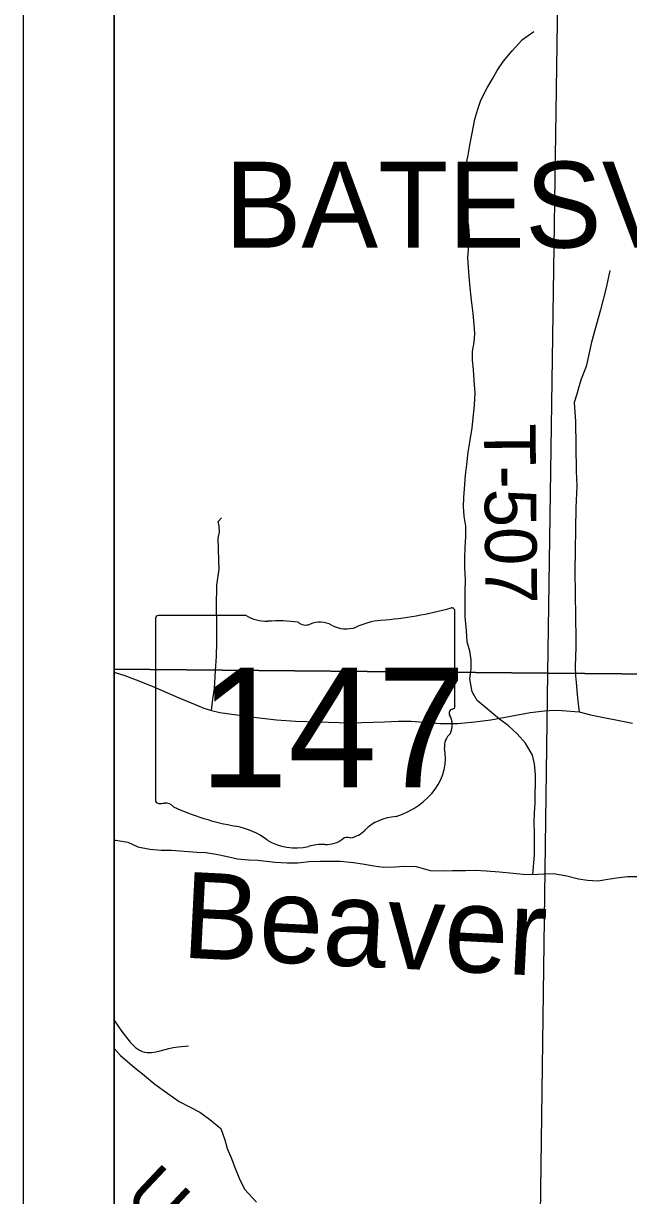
# Model space of a CAD drawing. Extents: x 0 to 34, y 0 to 22.
# Drawn here: x 23.417 to 24.083, y 17.051 to 18.342 of the extents above; entities that cross this region are included whole.
import ezdxf

# ---------------------------------------------------------------- set-up
doc = ezdxf.new("R2010")
doc.units = 0
for name, color, linetype in [('GM_X_Corporation', 7, 'Continuous'), ('GM_X_Corporation_Text', 7, 'Continuous'), ('GM_X_Minor_River', 7, 'Continuous'), ('GM_X_Minor_River_Text', 7, 'Continuous'), ('GM_X_State_Route', 7, 'Continuous'), ('GM_X_State_Shield', 7, 'Continuous'), ('GM_X_Township_Road', 7, 'Continuous'), ('GM_X_Township_Road_Text', 7, 'Continuous'), ('SH_Data', 7, 'Continuous')]:
    doc.layers.add(name, color=color, linetype=linetype)

msp = doc.modelspace()

# ---------------------------------------------------------------- linework, layer by layer
at = {"layer": 'GM_X_Corporation'}
msp.add_lwpolyline([(27.0234, 16.6611), (27.0349, 17.5522), (27.0419, 17.8236), (27.0487, 18.5805), (27.0719, 19.3912), (27.0733, 19.498), (27.0761, 19.6806), (27.0864, 20.0138), (27.0885, 20.1139), (27.0907, 20.123), (27.0873, 20.2665), (27.0031, 20.2673), (26.7822, 20.2704), (26.7196, 20.2707), (26.6351, 20.2734), (26.5702, 20.276), (26.2533, 20.2773), (25.4507, 20.2949), (24.5249, 20.3107), (24.0688, 20.3165), (24.0328, 20.3169), (23.5167, 20.3276), (23.5167, 14.5642)], dxfattribs=at)
msp.add_lwpolyline([(27.0234, 16.6611), (27.0349, 17.5522), (27.0419, 17.8236), (27.0487, 18.5805), (27.0719, 19.3912), (27.0733, 19.498), (27.0761, 19.6806), (27.0864, 20.0138), (27.0885, 20.1139), (27.0907, 20.123), (27.0873, 20.2665), (27.0031, 20.2673), (26.7822, 20.2704), (26.7196, 20.2707), (26.6351, 20.2734), (26.5702, 20.276), (26.2533, 20.2773), (25.4507, 20.2949), (24.5249, 20.3107), (24.0688, 20.3165), (24.0328, 20.3169), (23.5167, 20.3276), (23.5167, 14.5642)], dxfattribs=at)
for points in [[(23.5167, 18.6437), (23.5167, 17.6305), (23.994, 17.626), (24.0091, 18.6407)], [(24.0091, 18.6407), (25.0268, 18.6245), (25.0136, 17.617), (23.994, 17.626)], [(23.5167, 17.6305), (23.5167, 16.6012), (23.9803, 16.5962), (23.994, 17.626)], [(25.0136, 17.617), (24.9957, 16.5834), (23.9803, 16.5962), (23.994, 17.626)]]:
    msp.add_lwpolyline(points, close=True, dxfattribs=at)
at = {"layer": 'GM_X_Minor_River'}
for points in [[(23.9775, 17.4045), (23.9795, 17.4258), (23.9795, 17.4497), (23.9791, 17.4618), (23.9794, 17.4725), (23.9802, 17.4827), (23.9801, 17.4937), (23.9805, 17.5044), (23.9805, 17.5142), (23.9793, 17.5264), (23.9774, 17.5359), (23.9694, 17.5491), (23.9603, 17.5593), (23.9508, 17.568), (23.9409, 17.5756), (23.9165, 17.596), (23.9108, 17.6055), (23.9081, 17.6199), (23.9096, 17.6309), (23.9096, 17.6408), (23.9081, 17.6503), (23.9054, 17.6605), (23.9046, 17.6727), (23.903, 17.6886), (23.903, 17.716), (23.9033, 17.7289), (23.9029, 17.7421), (23.9029, 17.7535), (23.9032, 17.7646), (23.904, 17.7767), (23.9039, 17.7881), (23.902, 17.7991), (23.9012, 17.8097), (23.9016, 17.8196), (23.9023, 17.8291), (23.9034, 17.8443), (23.9049, 17.8561), (23.9064, 17.8697), (23.9083, 17.8808), (23.9109, 17.8963), (23.9124, 17.9108), (23.9135, 17.9214), (23.9142, 17.9351), (23.9131, 17.9487), (23.9123, 17.9605), (23.9111, 17.9711), (23.9111, 17.9806), (23.913, 17.9909), (23.9137, 18.0004), (23.9129, 18.0102), (23.9118, 18.0224), (23.9102, 18.0372), (23.9087, 18.0505), (23.9075, 18.063), (23.9067, 18.0729), (23.9059, 18.0839), (23.907, 18.0968), (23.9078, 18.1074), (23.907, 18.1181), (23.9058, 18.1276), (23.9046, 18.1397), (23.9031, 18.1526), (23.9019, 18.1636), (23.9023, 18.1743), (23.9038, 18.1845), (23.9064, 18.1967), (23.9083, 18.2077), (23.9109, 18.221), (23.9139, 18.2366), (23.9169, 18.2476), (23.9203, 18.2575), (23.9275, 18.2708), (23.9331, 18.2807), (23.9384, 18.2902), (23.9452, 18.3005), (23.9547, 18.3119), (23.9661, 18.3241), (23.9789, 18.3329)], [(23.5167, 17.4422), (23.5184, 17.4421), (23.5317, 17.4399), (23.5427, 17.435), (23.556, 17.4324), (23.5682, 17.4313), (23.5796, 17.4313), (23.5936, 17.4302), (23.608, 17.4291), (23.6175, 17.4284), (23.6289, 17.4269), (23.6395, 17.4247)], [(23.6395, 17.4247), (23.6524, 17.4217), (23.6646, 17.4206), (23.6748, 17.4202), (23.6938, 17.418), (23.7071, 17.4173), (23.7189, 17.4173), (23.731, 17.4185), (23.7435, 17.4189), (23.7659, 17.419), (23.7803, 17.4175), (23.7902, 17.416), (23.8027, 17.4138), (23.8134, 17.4123), (23.8259, 17.4127), (23.8357, 17.4135), (23.849, 17.4132), (23.8646, 17.4087), (23.879, 17.4084), (23.8893, 17.4088), (23.9033, 17.4088), (23.9143, 17.4092), (23.9264, 17.4085), (23.9409, 17.4074), (23.9561, 17.4059), (23.9671, 17.4048), (23.9765, 17.4045), (23.9898, 17.4049), (24.0005, 17.4053), (24.0149, 17.4027), (24.0278, 17.3997), (24.0377, 17.3982), (24.0494, 17.3975), (24.0604, 17.3991), (24.0726, 17.401), (24.082, 17.4022), (24.0927, 17.4022)], [(23.5167, 17.2127), (23.5235, 17.2049), (23.5368, 17.1935), (23.5498, 17.1829), (23.5612, 17.1735), (23.5756, 17.1629), (23.5882, 17.1542), (23.5996, 17.1485), (23.6109, 17.1425), (23.622, 17.1346), (23.6341, 17.1247), (23.6383, 17.1122), (23.641, 17.1024), (23.6456, 17.0914), (23.6494, 17.0815), (23.6544, 17.0698), (23.6601, 17.0576), (23.6734, 17.0433)]]:
    msp.add_lwpolyline(points, dxfattribs=at)
at = {"layer": 'GM_X_State_Route'}
msp.add_lwpolyline([(23.5167, 17.6269), (23.5178, 17.6267), (23.5282, 17.6236), (23.5409, 17.6189), (23.5583, 17.612), (23.587, 17.5993), (23.6059, 17.5915), (23.6154, 17.5877), (23.6237, 17.5849), (23.6329, 17.5828), (23.6518, 17.5803), (23.6732, 17.5774), (23.6954, 17.5746), (23.7163, 17.5732), (23.7766, 17.5714), (23.8144, 17.5727), (23.8297, 17.5734), (23.8435, 17.5732), (23.8753, 17.5708), (23.8946, 17.5707), (23.9136, 17.5725), (23.9314, 17.5748), (23.9747, 17.5827), (23.9904, 17.5848), (24.0009, 17.5853), (24.0099, 17.5849), (24.0286, 17.5835), (24.0411, 17.5803), (24.0875, 17.5711)], dxfattribs=at)
at = {"layer": 'GM_X_State_Shield'}
for p, q in [((23.8918, 17.5899), (23.8918, 17.6946)), ((23.5622, 17.6862), (23.5622, 17.4861)), ((23.662, 17.6897), (23.5655, 17.6897)), ((23.8918, 17.59), (23.8918, 17.5899))]:
    msp.add_line(p, q, dxfattribs=at)
for centre, major_axis, start_param, end_param in [((23.7744, 17.9625), (0.3495, 0), 4.814394, 5.042369), ((23.8882, 17.6951), (0.00367, 0), 6.141152, 7.989035), ((23.566, 17.6867), (0.00382, 0), 1.712693, 3.28349), ((23.685, 17.7129), (0.037, 0), 4.042523, 4.731795), ((23.6973, 17.5773), (0.133, 0), 1.404758, 1.657858), ((23.7274, 17.6877), (0.0107, 0), 3.836095, 5.185415), ((23.7431, 17.6646), (0.0222, 0), 0.950623, 2.079405), ((23.7718, 17.6963), (0.0267, 0), 4.081561, 5.145723), ((23.819, 17.6285), (0.0703, 0), 1.699011, 2.107814), ((23.8879, 17.5895), (0.00393, 0), 5.05454, 6.418171), ((23.891, 17.5823), (0.00568, 0), 1.883978, 3.671073), ((23.8548, 17.569), (0.0341, 0), 5.934695, 6.695948), ((23.905, 17.5461), (0.0248, 0), 2.387724, 3.262537), ((23.794, 17.5328), (0.0874, 0), 5.101752, 6.440018), ((23.566, 17.4857), (0.00385, 0), 3.00124, 4.508301), ((23.5666, 17.5061), (0.0294, 0), 4.665946, 4.897461), ((23.5726, 17.4746), (0.0106, 0), 0.519207, 1.627899), ((23.7065, 17.6544), (0.2524, 0), 4.195997, 4.488961), ((23.8308, 17.4299), (0.0479, 0), 1.647645, 2.488434), ((23.6312, 17.3962), (0.079, 0), 0.823519, 1.323587), ((23.7734, 17.4392), (0.00752, 0), 1.147584, 2.315152), ((23.7702, 17.4667), (0.0282, 0), 4.937069, 5.64225), ((23.7166, 17.4736), (0.0501, 0), 4.026481, 4.996735), ((23.7456, 17.4044), (0.0412, 0), 1.495662, 1.94098), ((23.7492, 17.4586), (0.0267, 0), 4.691044, 5.507374)]:
    msp.add_ellipse(centre, major_axis=major_axis, ratio=0.8, start_param=start_param, end_param=end_param, dxfattribs=at)
at = {"layer": 'GM_X_Township_Road'}
for points in [[(24.0625, 18.0697), (24.0585, 18.0508), (24.0523, 18.0265), (24.0424, 17.9909), (24.0365, 17.964), (24.031, 17.95), (24.0283, 17.9417), (24.026, 17.9334), (24.0232, 17.9243), (24.0245, 17.9033), (24.0255, 17.8486), (24.0262, 17.8325), (24.0248, 17.8082), (24.0237, 17.7386), (24.0249, 17.6636), (24.0248, 17.6549), (24.0244, 17.6334), (24.0246, 17.6232), (24.0252, 17.6158), (24.0263, 17.6029), (24.027, 17.5954), (24.0286, 17.5835)], [(23.6237, 17.5849), (23.6253, 17.5976), (23.627, 17.6091), (23.6283, 17.6286), (23.6291, 17.645), (23.6298, 17.66), (23.6295, 17.6793), (23.6291, 17.6996), (23.6295, 17.7229), (23.6322, 17.7406), (23.6319, 17.7508), (23.6311, 17.775), (23.6325, 17.7819), (23.6322, 17.7881), (23.631, 17.7932), (23.6347, 17.7973)], [(23.5167, 17.2435), (23.5168, 17.2433), (23.5251, 17.2312), (23.5341, 17.2195), (23.5399, 17.2137), (23.5444, 17.2107), (23.5475, 17.2095), (23.55, 17.2086), (23.5529, 17.2083), (23.5576, 17.2082), (23.5623, 17.2088), (23.5674, 17.21), (23.5769, 17.2127), (23.5817, 17.2139), (23.5871, 17.2146), (23.5986, 17.2156)]]:
    msp.add_lwpolyline(points, dxfattribs=at)
at = {"layer": 'SH_Data'}
for points in [[(23.4167, 21), (30.4167, 21), (30.4167, 14), (23.4167, 14)], [(23.5167, 20.9), (30.3167, 20.9), (30.3167, 14.1), (23.5167, 14.1)]]:
    msp.add_lwpolyline(points, close=True, dxfattribs=at)

# ---------------------------------------------------------------- texts
at = {"layer": 'GM_X_Corporation_Text'}
msp.add_text('BATESVILLE', height=0.0947, rotation=0, dxfattribs=at).set_placement((23.6383, 18.0949))
at = {"layer": 'GM_X_Minor_River_Text'}
msp.add_text('Beaver', height=0.0947, rotation=357.0891, dxfattribs=at).set_placement((23.59, 17.3129))
at = {"layer": 'GM_X_State_Shield'}
msp.add_text('147', height=0.13184, dxfattribs=at).set_placement((23.6101, 17.5002))
at = {"layer": 'GM_X_Township_Road_Text'}
for s, height, rotation, p in [('T-507', 0.05682, 270.5407, (23.9238, 17.9009)), ('U', 0.0568, 316.7209, (23.5258, 17.0471))]:
    msp.add_text(s, height=height, rotation=rotation, dxfattribs=at).set_placement(p)

doc.saveas('drawing.dxf')
